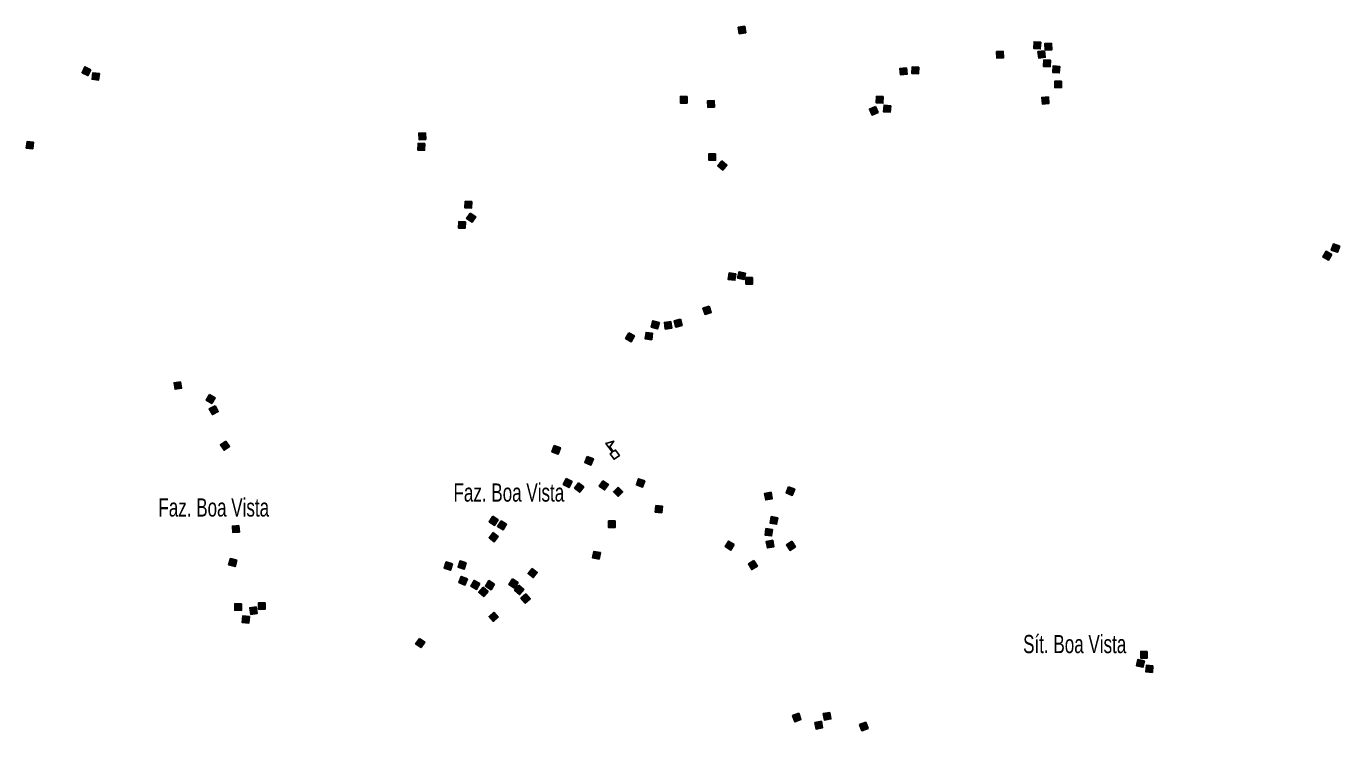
# Model space of a CAD drawing. Extents: x 679 to 705, y 7427.4 to 7455.4.
# Drawn here: x 692.93 to 698.7, y 7433.77 to 7436.87 of the extents above; entities that cross this region are included whole.
import ezdxf

# ---------------------------------------------------------------- set-up
doc = ezdxf.new("R2010")
doc.units = 0
doc.header["$LTSCALE"] = 0.032
doc.layers.add('2', color=7, linetype='Continuous', lineweight=25)
doc.layers.add('4', color=7, linetype='Continuous', lineweight=25)
doc.layers.add('61', color=7, linetype='Continuous')

msp = doc.modelspace()

# ---------------------------------------------------------------- hatches: boundary and pattern name
at = {"layer": '2'}
for points in [[(696.0884, 7436.8652), (696.0926, 7436.8365), (696.0639, 7436.8323), (696.0597, 7436.861)], [(697.3899, 7436.7949), (697.3878, 7436.766), (697.3589, 7436.7681), (697.361, 7436.797)], [(697.4375, 7436.7909), (697.4388, 7436.7619), (697.4098, 7436.7606), (697.4085, 7436.7896)], [(697.2243, 7436.7556), (697.2263, 7436.7266), (697.1973, 7436.7247), (697.1954, 7436.7536)], [(697.4061, 7436.7577), (697.4097, 7436.7289), (697.381, 7436.7253), (697.3774, 7436.7541)], [(693.2125, 7436.6741), (693.1996, 7436.6481), (693.1736, 7436.6611), (693.1866, 7436.6871)], [(696.7993, 7436.683), (696.8025, 7436.6542), (696.7737, 7436.651), (696.7705, 7436.6798)], [(696.8533, 7436.6855), (696.8525, 7436.6565), (696.8235, 7436.6572), (696.8243, 7436.6862)], [(697.4326, 7436.716), (697.431, 7436.687), (697.402, 7436.6886), (697.4036, 7436.7176)], [(697.4735, 7436.689), (697.4715, 7436.6601), (697.4426, 7436.6622), (697.4446, 7436.6911)], [(693.2502, 7436.6573), (693.2465, 7436.6285), (693.2177, 7436.6322), (693.2214, 7436.661)], [(697.4814, 7436.6236), (697.4806, 7436.5946), (697.4517, 7436.5953), (697.4524, 7436.6243)], [(695.8346, 7436.5565), (695.8346, 7436.5275), (695.8056, 7436.5275), (695.8056, 7436.5565)], [(696.697, 7436.5558), (696.6957, 7436.5269), (696.6667, 7436.5282), (696.668, 7436.5572)], [(697.4235, 7436.5549), (697.4262, 7436.526), (697.3973, 7436.5233), (697.3946, 7436.5521)], [(695.9534, 7436.5388), (695.9548, 7436.5099), (695.9259, 7436.5084), (695.9244, 7436.5374)], [(696.6626, 7436.5131), (696.6748, 7436.4868), (696.6485, 7436.4745), (696.6363, 7436.5008)], [(696.73, 7436.5158), (696.7272, 7436.4869), (696.6984, 7436.4896), (696.7011, 7436.5185)], [(694.6836, 7436.3969), (694.6853, 7436.368), (694.6563, 7436.3663), (694.6547, 7436.3953)], [(692.9605, 7436.3552), (692.9573, 7436.3264), (692.9284, 7436.3297), (692.9317, 7436.3585)], [(694.6806, 7436.3494), (694.6798, 7436.3204), (694.6508, 7436.3212), (694.6516, 7436.3502)], [(695.9597, 7436.3048), (695.9597, 7436.2758), (695.9307, 7436.2758), (695.9307, 7436.3048)], [(695.9877, 7436.2736), (696.01, 7436.255), (695.9914, 7436.2328), (695.9692, 7436.2513)], [(694.888, 7436.0942), (694.8864, 7436.0653), (694.8574, 7436.0669), (694.859, 7436.0959)], [(694.8811, 7436.0439), (694.9051, 7436.0275), (694.8887, 7436.0036), (694.8647, 7436.0199)], [(694.8597, 7436.0058), (694.8584, 7435.9769), (694.8295, 7435.9781), (694.8308, 7436.0071)], [(698.6697, 7435.8615), (698.6551, 7435.8365), (698.63, 7435.851), (698.6446, 7435.8761)], [(698.7049, 7435.8986), (698.6952, 7435.8713), (698.6679, 7435.8811), (698.6776, 7435.9084)], [(696.0483, 7435.7771), (696.0447, 7435.7483), (696.0159, 7435.7518), (696.0195, 7435.7806)], [(696.0914, 7435.7799), (696.0854, 7435.7515), (696.057, 7435.7576), (696.0631, 7435.786)], [(696.1225, 7435.7605), (696.1225, 7435.7315), (696.0935, 7435.7315), (696.0935, 7435.7605)], [(695.932, 7435.6347), (695.9411, 7435.6072), (695.9136, 7435.5981), (695.9045, 7435.6256)], [(695.7126, 7435.5624), (695.7049, 7435.5345), (695.677, 7435.5422), (695.6847, 7435.5701)], [(695.8052, 7435.578), (695.8126, 7435.5499), (695.7846, 7435.5425), (695.7771, 7435.5705)], [(695.578, 7435.5178), (695.6033, 7435.5036), (695.5891, 7435.4783), (695.5638, 7435.4925)], [(695.6829, 7435.5155), (695.6794, 7435.4868), (695.6506, 7435.4904), (695.6542, 7435.5191)], [(695.7635, 7435.5669), (695.7676, 7435.5382), (695.7389, 7435.5341), (695.7348, 7435.5628)], [(693.6073, 7435.3025), (693.6117, 7435.2739), (693.5831, 7435.2695), (693.5786, 7435.2981)], [(693.7345, 7435.2464), (693.7593, 7435.2314), (693.7443, 7435.2066), (693.7195, 7435.2217)], [(693.759, 7435.1971), (693.7724, 7435.1714), (693.7467, 7435.1579), (693.7333, 7435.1836)], [(693.8058, 7435.0415), (693.8223, 7435.0177), (693.7985, 7435.0012), (693.782, 7435.025)], [(695.2503, 7435.0215), (695.2776, 7435.0118), (695.2678, 7434.9845), (695.2405, 7434.9942)], [(695.3959, 7434.9742), (695.4227, 7434.963), (695.4115, 7434.9362), (695.3848, 7434.9474)], [(695.3032, 7434.8763), (695.329, 7434.863), (695.3157, 7434.8372), (695.2899, 7434.8505)], [(695.6484, 7434.8668), (695.6392, 7434.8393), (695.6117, 7434.8485), (695.6209, 7434.876)], [(695.3574, 7434.8574), (695.3802, 7434.8396), (695.3623, 7434.8167), (695.3395, 7434.8346)], [(695.4643, 7434.8671), (695.4883, 7434.8508), (695.472, 7434.8268), (695.448, 7434.8431)], [(695.5311, 7434.8393), (695.5516, 7434.8188), (695.5311, 7434.7983), (695.5106, 7434.8188)], [(696.281, 7434.8404), (696.308, 7434.8298), (696.2974, 7434.8028), (696.2704, 7434.8135)], [(696.2044, 7434.8163), (696.2094, 7434.7877), (696.1808, 7434.7828), (696.1758, 7434.8113)], [(694.9802, 7434.7107), (695.0044, 7434.6946), (694.9883, 7434.6705), (694.9641, 7434.6865)], [(695.7261, 7434.7548), (695.7232, 7434.726), (695.6944, 7434.7289), (695.6973, 7434.7577)], [(696.2331, 7434.7044), (696.2279, 7434.6759), (696.1994, 7434.6811), (696.2046, 7434.7096)], [(693.8637, 7434.6703), (693.8661, 7434.6414), (693.8372, 7434.639), (693.8348, 7434.6679)], [(695.0163, 7434.6909), (695.0408, 7434.6754), (695.0253, 7434.6509), (695.0008, 7434.6664)], [(695.5183, 7434.6902), (695.5183, 7434.6612), (695.4893, 7434.6612), (695.4893, 7434.6902)], [(696.2099, 7434.6533), (696.2065, 7434.6245), (696.1777, 7434.6279), (696.1811, 7434.6567)], [(694.9816, 7434.6392), (695.0045, 7434.6214), (694.9867, 7434.5985), (694.9638, 7434.6163)], [(696.0422, 7434.5869), (696.0271, 7434.5622), (696.0024, 7434.5772), (696.0174, 7434.602)], [(696.2114, 7434.6051), (696.2164, 7434.5766), (696.1878, 7434.5715), (696.1828, 7434.6001)], [(696.2954, 7434.6011), (696.3114, 7434.577), (696.2873, 7434.5609), (696.2712, 7434.585)], [(695.4531, 7434.5511), (695.4478, 7434.5226), (695.4193, 7434.5278), (695.4246, 7434.5564)], [(693.8539, 7434.5177), (693.8466, 7434.4897), (693.8185, 7434.497), (693.8259, 7434.5251)], [(694.8031, 7434.5015), (694.7948, 7434.4737), (694.767, 7434.4821), (694.7753, 7434.5099)], [(694.8637, 7434.5054), (694.8548, 7434.4778), (694.8272, 7434.4867), (694.8361, 7434.5143)], [(695.1531, 7434.4818), (695.1759, 7434.4639), (695.1581, 7434.441), (695.1352, 7434.4589)], [(696.1288, 7434.5166), (696.144, 7434.4919), (696.1193, 7434.4767), (696.1041, 7434.5014)], [(694.8685, 7434.4353), (694.8578, 7434.4084), (694.8308, 7434.4191), (694.8416, 7434.4461)], [(694.9228, 7434.4145), (694.9085, 7434.3893), (694.8833, 7434.4037), (694.8976, 7434.4289)], [(694.9876, 7434.4125), (694.9724, 7434.3878), (694.9477, 7434.403), (694.963, 7434.4277)], [(695.0668, 7434.435), (695.0914, 7434.4196), (695.076, 7434.395), (695.0514, 7434.4104)], [(694.9376, 7434.3989), (694.9596, 7434.38), (694.9407, 7434.358), (694.9187, 7434.3769)], [(695.095, 7434.4073), (695.117, 7434.3885), (695.0981, 7434.3665), (695.0761, 7434.3853)], [(695.1259, 7434.3694), (695.1449, 7434.3475), (695.123, 7434.3285), (695.104, 7434.3504)], [(693.8751, 7434.3258), (693.8743, 7434.2968), (693.8453, 7434.2976), (693.8461, 7434.3266)], [(693.94, 7434.3125), (693.9442, 7434.2838), (693.9155, 7434.2796), (693.9113, 7434.3083)], [(693.9784, 7434.3307), (693.979, 7434.3017), (693.95, 7434.3011), (693.9494, 7434.3301)], [(693.9095, 7434.2703), (693.9073, 7434.2414), (693.8784, 7434.2435), (693.8805, 7434.2725)], [(694.9853, 7434.2893), (695.0044, 7434.2675), (694.9826, 7434.2484), (694.9635, 7434.2702)], [(694.6572, 7434.1736), (694.6812, 7434.1573), (694.6649, 7434.1333), (694.6409, 7434.1497)], [(697.8458, 7434.075), (697.8392, 7434.0467), (697.811, 7434.0534), (697.8176, 7434.0816)], [(697.8585, 7434.1164), (697.8585, 7434.0874), (697.8295, 7434.0874), (697.8295, 7434.1164)], [(697.8836, 7434.0532), (697.8809, 7434.0243), (697.852, 7434.0271), (697.8548, 7434.0559)], [(696.3255, 7433.8446), (696.3356, 7433.8174), (696.3084, 7433.8074), (696.2983, 7433.8346)], [(696.4621, 7433.8485), (696.467, 7433.8199), (696.4385, 7433.815), (696.4336, 7433.8436)], [(696.4253, 7433.8094), (696.4307, 7433.7809), (696.4022, 7433.7754), (696.3968, 7433.8039)], [(696.6204, 7433.8054), (696.6308, 7433.7783), (696.6037, 7433.7679), (696.5933, 7433.795)]]:
    msp.add_hatch(color=256, dxfattribs=at).paths.add_polyline_path(points)

# ---------------------------------------------------------------- linework, layer by layer
for points in [[(696.0884, 7436.8652), (696.0926, 7436.8365), (696.0639, 7436.8323), (696.0597, 7436.861)], [(697.3899, 7436.7949), (697.3878, 7436.766), (697.3589, 7436.7681), (697.361, 7436.797)], [(697.4375, 7436.7909), (697.4388, 7436.7619), (697.4098, 7436.7606), (697.4085, 7436.7896)], [(697.2243, 7436.7556), (697.2263, 7436.7266), (697.1973, 7436.7247), (697.1954, 7436.7536)], [(697.4061, 7436.7577), (697.4097, 7436.7289), (697.381, 7436.7253), (697.3774, 7436.7541)], [(693.2125, 7436.6741), (693.1996, 7436.6481), (693.1736, 7436.6611), (693.1866, 7436.6871)], [(696.7993, 7436.683), (696.8025, 7436.6542), (696.7737, 7436.651), (696.7705, 7436.6798)], [(696.8533, 7436.6855), (696.8525, 7436.6565), (696.8235, 7436.6572), (696.8243, 7436.6862)], [(697.4326, 7436.716), (697.431, 7436.687), (697.402, 7436.6886), (697.4036, 7436.7176)], [(697.4735, 7436.689), (697.4715, 7436.6601), (697.4426, 7436.6622), (697.4446, 7436.6911)], [(693.2502, 7436.6573), (693.2465, 7436.6285), (693.2177, 7436.6322), (693.2214, 7436.661)], [(697.4814, 7436.6236), (697.4806, 7436.5946), (697.4517, 7436.5953), (697.4524, 7436.6243)], [(695.8346, 7436.5565), (695.8346, 7436.5275), (695.8056, 7436.5275), (695.8056, 7436.5565)], [(696.697, 7436.5558), (696.6957, 7436.5269), (696.6667, 7436.5282), (696.668, 7436.5572)], [(697.4235, 7436.5549), (697.4262, 7436.526), (697.3973, 7436.5233), (697.3946, 7436.5521)], [(695.9534, 7436.5388), (695.9548, 7436.5099), (695.9259, 7436.5084), (695.9244, 7436.5374)], [(696.6626, 7436.5131), (696.6748, 7436.4868), (696.6485, 7436.4745), (696.6363, 7436.5008)], [(696.73, 7436.5158), (696.7272, 7436.4869), (696.6984, 7436.4896), (696.7011, 7436.5185)], [(694.6836, 7436.3969), (694.6853, 7436.368), (694.6563, 7436.3663), (694.6547, 7436.3953)], [(692.9605, 7436.3552), (692.9573, 7436.3264), (692.9284, 7436.3297), (692.9317, 7436.3585)], [(694.6806, 7436.3494), (694.6798, 7436.3204), (694.6508, 7436.3212), (694.6516, 7436.3502)], [(695.9597, 7436.3048), (695.9597, 7436.2758), (695.9307, 7436.2758), (695.9307, 7436.3048)], [(695.9877, 7436.2736), (696.01, 7436.255), (695.9914, 7436.2328), (695.9692, 7436.2513)], [(694.888, 7436.0942), (694.8864, 7436.0653), (694.8574, 7436.0669), (694.859, 7436.0959)], [(694.8811, 7436.0439), (694.9051, 7436.0275), (694.8887, 7436.0036), (694.8647, 7436.0199)], [(694.8597, 7436.0058), (694.8584, 7435.9769), (694.8295, 7435.9781), (694.8308, 7436.0071)], [(698.6697, 7435.8615), (698.6551, 7435.8365), (698.63, 7435.851), (698.6446, 7435.8761)], [(698.7049, 7435.8986), (698.6952, 7435.8713), (698.6679, 7435.8811), (698.6776, 7435.9084)], [(696.0483, 7435.7771), (696.0447, 7435.7483), (696.0159, 7435.7518), (696.0195, 7435.7806)], [(696.0914, 7435.7799), (696.0854, 7435.7515), (696.057, 7435.7576), (696.0631, 7435.786)], [(696.1225, 7435.7605), (696.1225, 7435.7315), (696.0935, 7435.7315), (696.0935, 7435.7605)], [(695.932, 7435.6347), (695.9411, 7435.6072), (695.9136, 7435.5981), (695.9045, 7435.6256)], [(695.7126, 7435.5624), (695.7049, 7435.5345), (695.677, 7435.5422), (695.6847, 7435.5701)], [(695.8052, 7435.578), (695.8126, 7435.5499), (695.7846, 7435.5425), (695.7771, 7435.5705)], [(695.578, 7435.5178), (695.6033, 7435.5036), (695.5891, 7435.4783), (695.5638, 7435.4925)], [(695.6829, 7435.5155), (695.6794, 7435.4868), (695.6506, 7435.4904), (695.6542, 7435.5191)], [(695.7635, 7435.5669), (695.7676, 7435.5382), (695.7389, 7435.5341), (695.7348, 7435.5628)], [(693.6073, 7435.3025), (693.6117, 7435.2739), (693.5831, 7435.2695), (693.5786, 7435.2981)], [(693.7345, 7435.2464), (693.7593, 7435.2314), (693.7443, 7435.2066), (693.7195, 7435.2217)], [(693.759, 7435.1971), (693.7724, 7435.1714), (693.7467, 7435.1579), (693.7333, 7435.1836)], [(693.8058, 7435.0415), (693.8223, 7435.0177), (693.7985, 7435.0012), (693.782, 7435.025)], [(695.2503, 7435.0215), (695.2776, 7435.0118), (695.2678, 7434.9845), (695.2405, 7434.9942)], [(695.3959, 7434.9742), (695.4227, 7434.963), (695.4115, 7434.9362), (695.3848, 7434.9474)], [(695.3032, 7434.8763), (695.329, 7434.863), (695.3157, 7434.8372), (695.2899, 7434.8505)], [(695.6484, 7434.8668), (695.6392, 7434.8393), (695.6117, 7434.8485), (695.6209, 7434.876)], [(695.3574, 7434.8574), (695.3802, 7434.8396), (695.3623, 7434.8167), (695.3395, 7434.8346)], [(695.4643, 7434.8671), (695.4883, 7434.8508), (695.472, 7434.8268), (695.448, 7434.8431)], [(695.5311, 7434.8393), (695.5516, 7434.8188), (695.5311, 7434.7983), (695.5106, 7434.8188)], [(696.281, 7434.8404), (696.308, 7434.8298), (696.2974, 7434.8028), (696.2704, 7434.8135)], [(696.2044, 7434.8163), (696.2094, 7434.7877), (696.1808, 7434.7828), (696.1758, 7434.8113)], [(694.9802, 7434.7107), (695.0044, 7434.6946), (694.9883, 7434.6705), (694.9641, 7434.6865)], [(695.7261, 7434.7548), (695.7232, 7434.726), (695.6944, 7434.7289), (695.6973, 7434.7577)], [(696.2331, 7434.7044), (696.2279, 7434.6759), (696.1994, 7434.6811), (696.2046, 7434.7096)], [(693.8637, 7434.6703), (693.8661, 7434.6414), (693.8372, 7434.639), (693.8348, 7434.6679)], [(695.0163, 7434.6909), (695.0408, 7434.6754), (695.0253, 7434.6509), (695.0008, 7434.6664)], [(695.5183, 7434.6902), (695.5183, 7434.6612), (695.4893, 7434.6612), (695.4893, 7434.6902)], [(696.2099, 7434.6533), (696.2065, 7434.6245), (696.1777, 7434.6279), (696.1811, 7434.6567)], [(694.9816, 7434.6392), (695.0045, 7434.6214), (694.9867, 7434.5985), (694.9638, 7434.6163)], [(696.0422, 7434.5869), (696.0271, 7434.5622), (696.0024, 7434.5772), (696.0174, 7434.602)], [(696.2114, 7434.6051), (696.2164, 7434.5766), (696.1878, 7434.5715), (696.1828, 7434.6001)], [(696.2954, 7434.6011), (696.3114, 7434.577), (696.2873, 7434.5609), (696.2712, 7434.585)], [(695.4531, 7434.5511), (695.4478, 7434.5226), (695.4193, 7434.5278), (695.4246, 7434.5564)], [(693.8539, 7434.5177), (693.8466, 7434.4897), (693.8185, 7434.497), (693.8259, 7434.5251)], [(694.8031, 7434.5015), (694.7948, 7434.4737), (694.767, 7434.4821), (694.7753, 7434.5099)], [(694.8637, 7434.5054), (694.8548, 7434.4778), (694.8272, 7434.4867), (694.8361, 7434.5143)], [(695.1531, 7434.4818), (695.1759, 7434.4639), (695.1581, 7434.441), (695.1352, 7434.4589)], [(696.1288, 7434.5166), (696.144, 7434.4919), (696.1193, 7434.4767), (696.1041, 7434.5014)], [(694.8685, 7434.4353), (694.8578, 7434.4084), (694.8308, 7434.4191), (694.8416, 7434.4461)], [(694.9228, 7434.4145), (694.9085, 7434.3893), (694.8833, 7434.4037), (694.8976, 7434.4289)], [(694.9876, 7434.4125), (694.9724, 7434.3878), (694.9477, 7434.403), (694.963, 7434.4277)], [(695.0668, 7434.435), (695.0914, 7434.4196), (695.076, 7434.395), (695.0514, 7434.4104)], [(694.9376, 7434.3989), (694.9596, 7434.38), (694.9407, 7434.358), (694.9187, 7434.3769)], [(695.095, 7434.4073), (695.117, 7434.3885), (695.0981, 7434.3665), (695.0761, 7434.3853)], [(695.1259, 7434.3694), (695.1449, 7434.3475), (695.123, 7434.3285), (695.104, 7434.3504)], [(693.8751, 7434.3258), (693.8743, 7434.2968), (693.8453, 7434.2976), (693.8461, 7434.3266)], [(693.94, 7434.3125), (693.9442, 7434.2838), (693.9155, 7434.2796), (693.9113, 7434.3083)], [(693.9784, 7434.3307), (693.979, 7434.3017), (693.95, 7434.3011), (693.9494, 7434.3301)], [(693.9095, 7434.2703), (693.9073, 7434.2414), (693.8784, 7434.2435), (693.8805, 7434.2725)], [(694.9853, 7434.2893), (695.0044, 7434.2675), (694.9826, 7434.2484), (694.9635, 7434.2702)], [(694.6572, 7434.1736), (694.6812, 7434.1573), (694.6649, 7434.1333), (694.6409, 7434.1497)], [(697.8458, 7434.075), (697.8392, 7434.0467), (697.811, 7434.0534), (697.8176, 7434.0816)], [(697.8585, 7434.1164), (697.8585, 7434.0874), (697.8295, 7434.0874), (697.8295, 7434.1164)], [(697.8836, 7434.0532), (697.8809, 7434.0243), (697.852, 7434.0271), (697.8548, 7434.0559)], [(696.3255, 7433.8446), (696.3356, 7433.8174), (696.3084, 7433.8074), (696.2983, 7433.8346)], [(696.4621, 7433.8485), (696.467, 7433.8199), (696.4385, 7433.815), (696.4336, 7433.8436)], [(696.4253, 7433.8094), (696.4307, 7433.7809), (696.4022, 7433.7754), (696.3968, 7433.8039)], [(696.6204, 7433.8054), (696.6308, 7433.7783), (696.6037, 7433.7679), (696.5933, 7433.795)]]:
    msp.add_lwpolyline(points, close=True, dxfattribs=at)
at = {"layer": '4'}
for points in [[(695.506, 7434.992), (695.4777, 7435.0312), (695.5119, 7435.0417), (695.4947, 7435.016), (695.51, 7434.9949)], [(695.51, 7434.9949), (695.5198, 7435.0019), (695.5368, 7434.9784), (695.5133, 7434.9615), (695.4963, 7434.985), (695.506, 7434.992)]]:
    msp.add_lwpolyline(points, dxfattribs=at)

# ---------------------------------------------------------------- texts
at = {"layer": '61', "width": 0.7}
for s, p in [('Faz. Boa Vista', (694.8073, 7434.7752)), ('Faz. Boa Vista', (693.5094, 7434.7095)), ('Sít. Boa Vista', (697.3125, 7434.109))]:
    msp.add_text(s, height=0.08, dxfattribs=at).set_placement(p)

doc.saveas('drawing.dxf')
